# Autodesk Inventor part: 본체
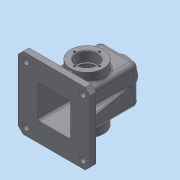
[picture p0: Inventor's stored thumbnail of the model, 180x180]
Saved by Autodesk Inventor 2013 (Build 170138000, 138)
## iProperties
Created: 2018-10
Part Number: 본체
Material: 일반
Document SubType Name: Modeling
Designer: Administrator
Density: 1 g/cm^3
Author: Administrator
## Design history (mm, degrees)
sketch "스케치1"
  geometry: L1 (-32.5, 55)-(32.5, 55); L2 (32.5, 55)-(32.5, -55); L3 (32.5, -55)-(-32.5, -55); L4 (-32.5, -55)-(-32.5, 55); C1 r 27.5 at (0, 0); 2 further points
  constraints: 8 end point, 2 parallel, 1 centre point, 1 coincident, 1 horizontal, 1 midpoint, 1 perpendicular, 1 vertical alignment
  dimensions: "d0" = 55 diameter of C1; "d1" = 65 distance of L2.end L3.end; "d2" = 110 distance of L3.end L1.start; "d3" = 55 distance from line of L3 point (0, 0)
extrude "돌출1" new body sketch "스케치1" stored distance "d4" = 65; taper "d5" = 0 deg
sketch "스케치2" dims "d98" = 95, "d99" = 95
  geometry: L1 (5, -5)-(60, -5); L2 (60, -5)-(60, -60); L3 (60, -60)-(5, -60); L4 (5, -60)-(5, -5); L5 (5, -5)-(60, -60); L6 (60, -5)-(5, -60); 1 further point
  constraints: 12 end point, 2 midpoint, 2 parallel, 1 horizontal, 1 perpendicular
  dimensions: "d6" = 55 distance of L2.end L3.end; "d7" = 55 distance of L1.end L2.end
extrude "돌출2" cut sketch "스케치2" distance "d8" = 105; taper "d9" = 0 deg
fillet "모깎기3" dims "d12" = 3
fillet "모깎기4" dims "d13" = 3
sketch "스케치5"
  geometry: L1 (65, 0)-(65, -65) reference; L2 (0, 0)-(65, 0) reference; L3 (0, 0)-(0, -65) reference; L4 (65, -65)-(0, -65) reference; L5 (-27.5, 27.5)-(92.5, 27.5); L6 (92.5, 27.5)-(92.5, -92.5); L7 (92.5, -92.5)-(-27.5, -92.5); L8 (-27.5, -92.5)-(-27.5, 27.5); L9 (-27.5, 27.5)-(92.5, -92.5); L10 (92.5, 27.5)-(-27.5, -92.5); 1 further point
  constraints: 12 end point, 2 midpoint, 2 parallel, 1 horizontal, 1 perpendicular
  dimensions: "d22" = 120 distance of L6.end L7.end; "d23" = 120 distance of L5.end L6.end
extrude "돌출4" join sketch "스케치5" distance "d24" = 10; taper "d25" = 0 deg
sketch "스케치6"
  geometry: C1 r 27.5 at (0, 0); 1 further point
  constraints: 1 centre point, 1 coincident
  dimensions: "d26" = 55 diameter of C1
extrude "돌출5" join sketch "스케치6" distance "d27" = 15; taper "d28" = 0 deg
hole "구멍1" diameter "d31" = 30; stored, may be unused: countersink angle "d35" = 90 deg, drill point angle "d37" = 118 deg; dims "d29" = 10, "d30" = 10, "d32" = 6, "d33" = 35, "d34" = 17, "d36" = 8
sketch "스케치7"
  geometry: C1 r 17.5 at (0, 0) reference; 1 further point
  constraints: 1 vertical alignment
  dimensions: "d38" = 21 distance of C1.centre point (0, 21)
hole "구멍2" sketch "스케치7" at (0, 21) diameter "d39" = 3.242; stored, may be unused: countersink angle "d43" = 90 deg, drill point angle "d45" = 118 deg; dims "d40" = 8, "d41" = 35, "d42" = 17, "d44" = 10
fillet "모깎기5" dims "d49" = 8
fillet "모깎기6" dims "d50" = 8
node "작업 평면1"
sketch "스케치8"
  geometry: C1 r 20 at (60, -60); 1 further point
  constraints: 1 centre point, 1 coincident
  dimensions: "d52" = 40 diameter of C1
extrude "돌출6" join sketch "스케치8" stored distance "d53" = 15; taper "d54" = 7 deg
hole "구멍3" diameter "d57" = 22.835; stored, may be unused: countersink angle "d61" = 90 deg, drill point angle "d63" = 118 deg; dims "d55" = 10, "d56" = 10, "d58" = 8, "d59" = 35, "d60" = 17, "d62" = 10
chamfer "모따기2" distance "d64" = 8; stored, may be unused: second distance "d65" = 2, angle "d66" = 45 deg
chamfer "모따기3" distance "d67" = 8; stored, may be unused: second distance "d68" = 2, angle "d69" = 45 deg
sketch "스케치9"
  geometry: L1 (-48, -45)-(-42.894, -16.04); L2 (-60, -45)-(-60, -55) reference; L3 (-52, -45)-(52, -45) reference; 1 further point
  constraints: 2 end point, 1 point on line
  dimensions: "d70" = 12 distance from line of L2 L1.start; "d73" = 10 deg angle of L2 L1
feature "리브1" sketch "스케치9" dims "d74" = 1, "d75" = 10, "d76" = 0, "d77" = 0, "d78" = 1, "d79" = 1
sketch "스케치11"
  geometry: L1 (-41, 42.5)-(-34, 42.5); L2 (47, 27.5)-(-55, 27.5) reference; 1 further point
  constraints: 2 end point, 1 horizontal
  dimensions: "d81" = 15 distance between parallel lines of L1 L2
feature "리브2" sketch "스케치11" dims "d82" = 1, "d83" = 6, "d84" = 0, "d85" = 0, "d86" = 1, "d87" = 1
fillet "모깎기7" dims "d88" = 3
fillet "모깎기8" dims "d89" = 3
fillet "모깎기9" dims "d90" = 3
fillet "모깎기10" dims "d91" = 3
fillet "모깎기11" dims "d92" = 1
fillet "모깎기12" dims "d93" = 3
fillet "모깎기13" dims "d94" = 3
chamfer "모따기4" distance "d95" = 1; stored, may be unused: second distance "d96" = 2, angle "d97" = 45 deg
sketch "스케치12"
  geometry: L1 (4.5, 107.5)-(99.5, 107.5); L2 (99.5, 107.5)-(99.5, 12.5); L3 (99.5, 12.5)-(4.5, 12.5); L4 (4.5, 12.5)-(4.5, 107.5); L5 (4.5, 107.5)-(99.5, 12.5); L6 (99.5, 107.5)-(4.5, 12.5); 5 further points
  constraints: 12 end point, 4 coincident, 2 midpoint, 2 parallel, 1 horizontal, 1 perpendicular
  dimensions: "d98" = 95 distance of L2.end L3.end; "d99" = 95 distance of L1.end L2.end
hole "구멍4" sketch "스케치12" at (4.5, 107.5), (99.5, 107.5), (99.5, 12.5), (4.5, 12.5) diameter "d100" = 10; stored, may be unused: countersink angle "d104" = 90 deg, drill point angle "d106" = 118 deg; dims "d101" = 8, "d102" = 35, "d103" = 17, "d105" = 10
fillet "모깎기14" dims "d107" = 3
chamfer "모따기5" distance "d108" = 1; stored, may be unused: second distance "d109" = 2, angle "d110" = 45 deg
sketch "스케치13"
  geometry: L1 (20, 65)-(-20, 65) reference; L2 (-32.5, 47)-(-32.5, -44) reference; 1 further point
  constraints: 1 other
  dimensions: "d111" = 26 distance from line of point (0, 39) L1; "d112" = 32.5 distance from line of L2 point (0, 39)
feature "엠보싱1" sketch "스케치13" dims "d0" = 55, "d113" = 0.5, "d114" = 0
node "솔리드1"
pattern_circular "원형 패턴1" dims angle "d47" = 360 deg
mirror "대칭1"
mirror "대칭2"
mirror "대칭3"
